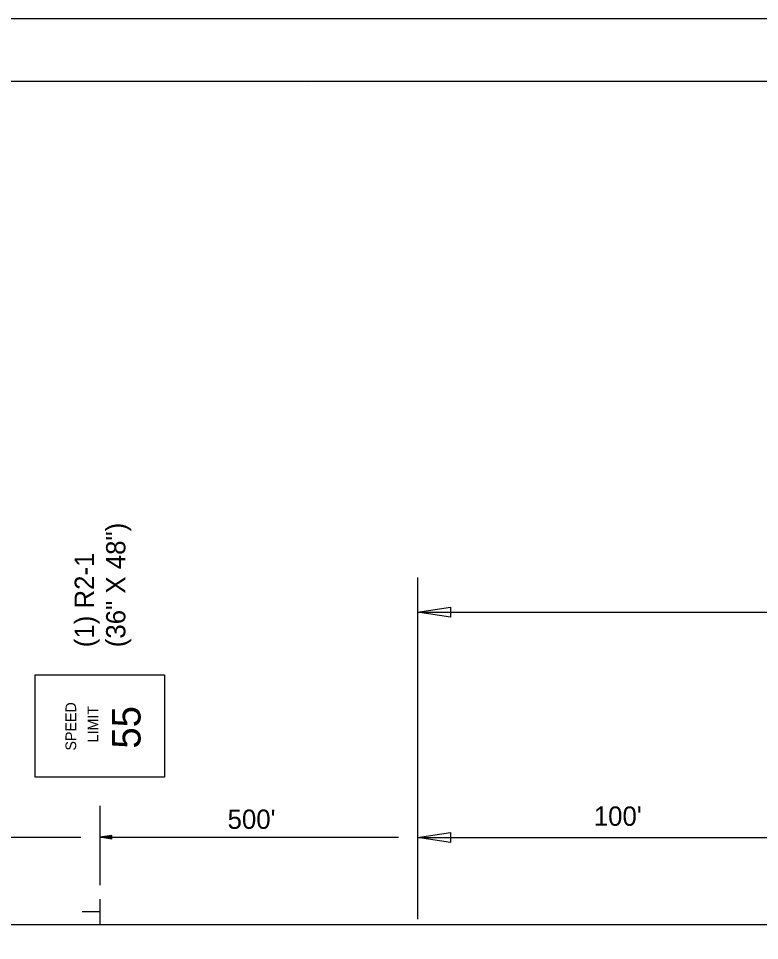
# Model space of a CAD drawing. Extents: x 1678017 to 1687792, y 404433 to 413488.
# Drawn here: x 1678979.75 to 1679002.8, y 409298.92 to 409327.59 of the extents above; entities that cross this region are included whole.
import ezdxf

# ---------------------------------------------------------------- set-up
doc = ezdxf.new("R2010")
doc.units = 0
for name, color, linetype in [('Default', 7, 'Continuous'), ('S_BUILDING', 7, 'Continuous'), ('S_STREAM', 7, 'Continuous')]:
    doc.layers.add(name, color=color, linetype=linetype)

msp = doc.modelspace()

# ---------------------------------------------------------------- linework, layer by layer
at = {"layer": 'Default'}
for p, q in [((1678992.164, 409310.209), (1678992.164, 409299.586)), ((1678992.164, 409309.13), (1678993.194, 409309.285)), ((1678992.164, 409309.13), (1679044.482, 409309.13)), ((1678993.194, 409308.976), (1678992.164, 409309.13)), ((1678993.194, 409309.285), (1678993.194, 409308.976)), ((1678982.279, 409303.107), (1678982.279, 409300.634)), ((1678992.164, 409302.124), (1678993.194, 409302.279)), ((1678993.194, 409302.279), (1678993.194, 409301.969)), ((1678972.614, 409302.128), (1678981.688, 409302.128)), ((1678982.654, 409302.184), (1678982.279, 409302.128)), ((1678982.279, 409302.128), (1678991.571, 409302.128)), ((1678982.654, 409302.072), (1678982.279, 409302.128)), ((1678982.654, 409302.175), (1678982.342, 409302.128)), ((1678982.654, 409302.081), (1678982.342, 409302.128)), ((1678982.654, 409302.165), (1678982.406, 409302.128)), ((1678982.654, 409302.091), (1678982.406, 409302.128)), ((1678982.654, 409302.156), (1678982.469, 409302.128)), ((1678982.654, 409302.1), (1678982.469, 409302.128)), ((1678982.654, 409302.147), (1678982.532, 409302.128)), ((1678982.654, 409302.11), (1678982.532, 409302.128)), ((1678982.654, 409302.137), (1678982.595, 409302.128)), ((1678982.654, 409302.119), (1678982.595, 409302.128)), ((1678982.654, 409302.072), (1678982.654, 409302.184)), ((1678993.194, 409301.969), (1678992.164, 409302.124)), ((1678992.164, 409302.124), (1679004.592, 409302.124)), ((1678982.279, 409300.199), (1678982.279, 409299.416)), ((1678982.268, 409299.81), (1678981.733, 409299.81)), ((1678938.648, 409299.416), (1679044.482, 409299.416))]:
    msp.add_line(p, q, dxfattribs=at)
msp.add_lwpolyline([(1678980.27, 409307.181), (1678984.288, 409307.181), (1678984.288, 409303.993), (1678980.27, 409303.993)], close=True, dxfattribs=at)
at = {"layer": 'S_BUILDING'}
for p, q in [((1678912.52, 409325.639), (1679070.61, 409325.639)), ((1678988.78, 409325.509), (1678988.78, 409325.509)), ((1678988.78, 409325.509), (1678988.78, 409325.509))]:
    msp.add_line(p, q, dxfattribs=at)
at = {"layer": 'S_STREAM'}
msp.add_line((1678906.32, 409327.586), (1679072.986, 409327.586), dxfattribs=at)
for points in [[(1678906.316, 409327.586), (1679072.986, 409327.586), (1679072.986, 409220.917), (1678906.316, 409220.917)], [(1679029.48, 409325.639), (1679039.29, 409325.639), (1679039.29, 409320.699), (1679047.346, 409320.699), (1679058.946, 409320.699), (1679058.946, 409308.532), (1679070.61, 409308.532), (1679070.61, 409222.909), (1678912.52, 409222.909), (1678912.52, 409325.639)]]:
    msp.add_lwpolyline(points, close=True, dxfattribs=at)

# ---------------------------------------------------------------- texts
at = {"layer": 'Default'}
for s, height, p in [('(36" X 48")', 0.6, (1678983.076, 409308.036)), ('(1) R2-1', 0.6, (1678982.098, 409308.036)), ('SPEED', 0.332, (1678981.545, 409304.823)), ('LIMIT', 0.332, (1678982.231, 409305.077)), ('55', 0.8897, (1678983.547, 409304.884))]:
    msp.add_text(s, height=height, rotation=90, dxfattribs=at).set_placement(p)
for s, p in [("100'", (1678997.646, 409302.485)), ("500'", (1678986.255, 409302.389))]:
    msp.add_text(s, height=0.6, dxfattribs=at).set_placement(p)

doc.saveas('drawing.dxf')
